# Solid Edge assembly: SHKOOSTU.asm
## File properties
Author: Türk
Template: Iso Assembly.asm
Last saved by: Türk
Revision: 14
Application: Solid Edge
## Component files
Shockabsorber.par
ShKolvikoostu.asm
Shkaan.par
Poldikoostu5.asm
Esimene vedru.par
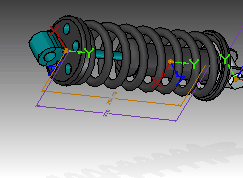
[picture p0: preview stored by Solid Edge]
